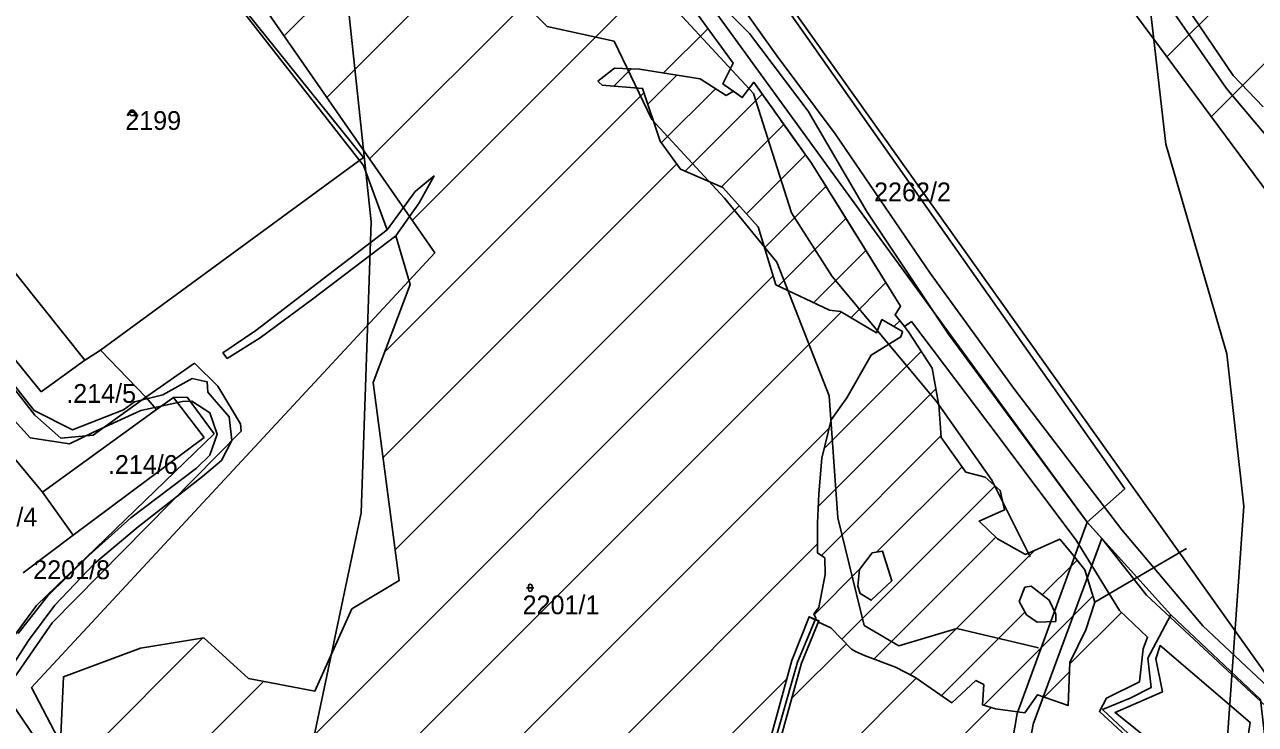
# Model space of a CAD drawing. Extents: x -564810 to -550519, y -1045831 to -1034011.
# Drawn here: x -553141.5 to -552807.2, y -1037088.7 to -1036898.7 of the extents above; entities that cross this region are included whole.
import ezdxf

# ---------------------------------------------------------------- set-up
doc = ezdxf.new("R2010")
doc.units = 0
for name, color, linetype in [('KN stav', 7, 'Continuous'), ('Lesní porost', 7, 'Continuous'), ('Odvodněné plochy', 7, 'Continuous'), ('Parcelní čísla', 7, 'Continuous'), ('Polní cesty stavající', 7, 'Continuous'), ('přeložka st silnice', 7, 'Continuous'), ('STG', 7, 'Continuous'), ('Vodní plocha', 7, 'Continuous'), ('vodní toky', 7, 'Continuous'), ('Vrstva 22', 7, 'Continuous'), ('Vrstva 33', 7, 'Continuous'), ('Vrstva 5', 7, 'Continuous'), ('zamokř ploch', 7, 'Continuous')]:
    doc.layers.add(name, color=color, linetype=linetype)

msp = doc.modelspace()

# ---------------------------------------------------------------- linework, layer by layer
at = {"layer": 'KN stav'}
for p, q in [((-553049.46, -1036934.72), (-553108.12, -1036861.74)), ((-553108.12, -1036861.74), (-553049.46, -1036934.72)), ((-552953.24, -1036867.58), (-552842.6, -1037024.79)), ((-552967.16, -1036876.79), (-552909.89, -1036955.71)), ((-552909.89, -1036955.71), (-552967.16, -1036876.79)), ((-553179.8, -1036921.43), (-553125.14, -1036989.83)), ((-553191.76, -1036930.97), (-553137.02, -1036998.43)), ((-553138.69, -1037004.7), (-553194.93, -1036933.35)), ((-553120.91, -1036987.1), (-553049.46, -1036934.72)), ((-553049.46, -1036934.72), (-553120.91, -1036987.1)), ((-552909.89, -1036955.71), (-552852.84, -1037033.78)), ((-552852.84, -1037033.78), (-552909.89, -1036955.71)), ((-553124.73, -1036989.54), (-553120.91, -1036987.1)), ((-553108.56, -1036999.88), (-553120.91, -1036987.1)), ((-553120.91, -1036987.1), (-553108.56, -1036999.88)), ((-553136.61, -1036998.14), (-553125.14, -1036989.83)), ((-553125.14, -1036989.83), (-553124.73, -1036989.54)), ((-553095.38, -1036990.58), (-553108.56, -1036999.88)), ((-553108.56, -1036999.88), (-553095.38, -1036990.58)), ((-553089.01, -1036996.83), (-553095.38, -1036990.58)), ((-553095.38, -1036990.58), (-553089.01, -1036996.83)), ((-553137.02, -1036998.43), (-553136.61, -1036998.14)), ((-553082.9, -1037007.12), (-553089.01, -1036996.83)), ((-553089.01, -1036996.83), (-553082.9, -1037007.12)), ((-553108.56, -1036999.88), (-553122.91, -1037010.18)), ((-553108.56, -1036999.88), (-553105.68, -1037003.24)), ((-553105.68, -1037003.24), (-553101.1, -1036999.92)), ((-553097.34, -1036999.88), (-553101.1, -1036999.92)), ((-553101.1, -1036999.92), (-553092.72, -1037010.79)), ((-553090.03, -1037009.79), (-553097.34, -1036999.88)), ((-553131.68, -1037010.98), (-553138.69, -1037004.7)), ((-553136.66, -1037025.67), (-553105.68, -1037003.24)), ((-553082.7, -1037009.12), (-553082.9, -1037007.12)), ((-553082.9, -1037007.12), (-553082.7, -1037009.12)), ((-553150.62, -1037008.84), (-553136.66, -1037025.67)), ((-553138.24, -1037056.46), (-553090.03, -1037009.79)), ((-553134.05, -1037061.18), (-553082.7, -1037009.12)), ((-553082.7, -1037009.12), (-553134.05, -1037061.18)), ((-553122.91, -1037010.18), (-553131.68, -1037010.98)), ((-553092.72, -1037010.79), (-553128.33, -1037037.33)), ((-552842.6, -1037024.79), (-552852.84, -1037033.78)), ((-553136.66, -1037025.67), (-553128.33, -1037037.33)), ((-552852.84, -1037033.78), (-552871.88, -1037085.78)), ((-552871.88, -1037085.78), (-552852.84, -1037033.78)), ((-552852.84, -1037033.78), (-552848.85, -1037038.19)), ((-553128.33, -1037037.33), (-553141.88, -1037047.57)), ((-552848.85, -1037038.19), (-552867.52, -1037088.69)), ((-552848.85, -1037038.19), (-552836.74, -1037053.6)), ((-552836.74, -1037053.6), (-552803.1, -1037084.94)), ((-553145.77, -1037066.62), (-553138.24, -1037056.46)), ((-553147.77, -1037081.04), (-553134.05, -1037061.18)), ((-553134.05, -1037061.18), (-553147.77, -1037081.04)), ((-552871.88, -1037085.78), (-552882.56, -1037148.8)), ((-552882.56, -1037148.8), (-552871.88, -1037085.78)), ((-552867.52, -1037088.69), (-552871.98, -1037113))]:
    msp.add_line(p, q, dxfattribs=at)
at = {"layer": 'Lesní porost'}
for p, q in [((-553071.01, -1036901.75), (-552990.73, -1036821.47)), ((-553059.41, -1036918.44), (-552978.32, -1036837.34)), ((-553047.82, -1036935.13), (-552965.78, -1036853.08)), ((-553036.23, -1036951.82), (-552964.65, -1036880.24)), ((-552967.92, -1036911.79), (-552955.85, -1036899.73)), ((-553043.69, -1036987.57), (-552973.24, -1036917.12)), ((-553044.16, -1037016.32), (-552964.35, -1036936.51)), ((-553040.87, -1037041.32), (-552947.4, -1036947.85)), ((-553108.48, -1037137.2), (-552938.17, -1036966.9)), ((-553103.39, -1037160.4), (-552919.72, -1036976.73)), ((-553070.11, -1037155.41), (-552922.98, -1037008.28)), ((-553060.69, -1037174.28), (-552926.08, -1037039.67)), ((-552850.78, -1037055.55), (-552825.91, -1037040.95)), ((-552857.62, -1037072.35), (-552843.57, -1037058.3)), ((-553127.99, -1037100.15), (-553093.08, -1037065.24)), ((-552933.14, -1037081.73), (-552918.27, -1037066.85)), ((-553118.23, -1037118.68), (-553076.6, -1037077.04)), ((-553038.67, -1037180.54), (-552934.45, -1037076.31)), ((-552949.97, -1037126.84), (-552899.29, -1037076.16)), ((-552970.05, -1037175.2), (-552878.98, -1037084.13))]:
    msp.add_line(p, q, dxfattribs=at)
for points in [[(-553142.91, -1037094.55), (-553139.29, -1037099.69), (-553142.45, -1037101.46), (-553113.25, -1037154.18), (-553102.58, -1037148.29), (-553131.8, -1037095.67), (-553130.98, -1037075.85), (-553110.01, -1037068.01), (-553092.81, -1037065.2), (-553080.66, -1037076.27), (-553062.63, -1037079.69), (-553052.57, -1037057.35), (-553039.77, -1037049.68), (-553046.85, -1036995.87), (-553036.74, -1036969.29), (-553040.68, -1036956.03), (-553034.35, -1036947.04), (-553030.25, -1036939.75), (-553035.39, -1036944.01), (-553043.05, -1036954.42), (-553049.43, -1036936.91), (-553085.28, -1036891.02)], [(-552958.5, -1036896.1), (-552948.99, -1036909.12), (-552951.83, -1036914.72), (-552946.54, -1036918.5), (-552943.44, -1036914.31), (-552927.71, -1036936.31), (-552903.54, -1036975.12), (-552905.06, -1036977.48), (-552902.52, -1036980.62), (-552900.59, -1036979.32), (-552879.86, -1037006.72), (-552855.84, -1037038.66), (-552844.11, -1037057.79), (-552836.45, -1037065), (-552837.66, -1037068.23), (-552838.67, -1037077.19), (-552847.62, -1037081.64), (-552849.55, -1037085.22)], [(-552939.26, -1037103.77), (-552930.48, -1037072.14), (-552925.72, -1037060.62), (-552928.41, -1037059.51), (-552933.09, -1037071.34), (-552941.77, -1037103.14)], [(-552810.24, -1037099.06), (-552808.61, -1037088.2), (-552833.03, -1037067.34), (-552834.22, -1037070.92), (-552832.38, -1037079.88), (-552845.29, -1037085.51), (-552828.27, -1037099.13)], [(-552849.55, -1037085.22), (-552830.17, -1037103.17), (-552816.47, -1037118.81), (-552817.67, -1037133.71), (-552823.79, -1037143.46), (-552852.83, -1037178.07), (-552873.47, -1037198.62), (-552891.1, -1037218.45), (-552901.83, -1037239.56), (-552906.62, -1037243.7), (-552906.02, -1037249.45), (-552916.79, -1037279.9), (-552921.02, -1037281.63), (-552922.55, -1037284.1), (-552922.87, -1037294.35), (-552927.53, -1037313.12), (-552933.23, -1037342.22), (-552937.38, -1037370), (-552936.66, -1037373.95)]]:
    msp.add_lwpolyline(points, dxfattribs=at)
at = {"layer": 'Odvodněné plochy'}
msp.add_lwpolyline([(-551958.26, -1037299.6), (-552014.39, -1037387.96), (-552071.44, -1037439.67), (-552181.86, -1037352.69), (-552220.51, -1037328.76), (-552305.17, -1037262.49), (-552417.43, -1037128.11), (-552540.73, -1037034.23), (-552612.51, -1036967.96), (-552627.23, -1037012.14), (-552687.96, -1037100.5), (-552930.89, -1036772.83)], dxfattribs=at)
at = {"layer": 'Polní cesty stavající'}
for p, q in [((-552813.18, -1036912.44), (-552855.7, -1036849.82)), ((-552859.35, -1036851.96), (-552815.01, -1036915.99)), ((-552805.04, -1036920.98), (-552813.18, -1036912.44)), ((-552815.01, -1036915.99), (-552777.75, -1036960.4))]:
    msp.add_line(p, q, dxfattribs=at)
for points in [[(-553168.93, -1036965.42), (-553138.92, -1037003.49), (-553128.48, -1037008.7), (-553114.68, -1037003.31), (-553111.69, -1037001.07), (-553103.94, -1036999.25), (-553096.03, -1036994.82), (-553091.92, -1036995.64), (-553091.7, -1036998.53), (-553085.93, -1037005.2), (-553085.2, -1037011.59), (-553088.05, -1037017.03), (-553093.14, -1037021.41), (-553110.66, -1037035.09), (-553122.55, -1037044.98), (-553133.33, -1037056.36), (-553140.45, -1037065.93), (-553146.62, -1037075.52)], [(-553143.23, -1037064.08), (-553135.24, -1037053.88), (-553124.09, -1037042.84), (-553112.68, -1037032.66), (-553094.83, -1037019.16), (-553091.16, -1037015.57), (-553089.23, -1037009.91), (-553091.19, -1037004.1), (-553096.04, -1037000.9), (-553098.57, -1037001), (-553109.94, -1037003.45), (-553123.01, -1037009.48), (-553129.3, -1037012.54), (-553139.96, -1037010.87), (-553144.33, -1037006.11)], [(-553147.02, -1037079.93), (-553135.16, -1037097.46), (-553139.29, -1037099.69), (-553142.91, -1037094.55)]]:
    msp.add_lwpolyline(points, dxfattribs=at)
at = {"layer": 'přeložka st silnice'}
for p, q in [((-552831.15, -1036907.36), (-552711.44, -1036787.65)), ((-552819.1, -1036923.6), (-552699.32, -1036803.82))]:
    msp.add_line(p, q, dxfattribs=at)
at = {"layer": 'STG'}
for points in [[(-553086.83, -1037509.03), (-553102.44, -1037299.55), (-553086.83, -1037209.51), (-553071.21, -1037131.41), (-553050.08, -1037031.26), (-553047.33, -1036952.24), (-553054.68, -1036883.33), (-553078.56, -1036837.39), (-553119.89, -1036809.83), (-553157.55, -1036794.21), (-553196.13, -1036789.62), (-553152.96, -1036760.21), (-553125.41, -1036746.43), (-553070.29, -1036720.71), (-552977.52, -1036697.74), (-552896.69, -1036677.52), (-552848, -1036668.34), (-552776.36, -1036649.96), (-552684.5, -1036608.61), (-552638.57, -1036588.4), (-552609.18, -1036560.84), (-552571.52, -1036514.9), (-552546.72, -1036489.17)], [(-552837.9, -1036875.06), (-552831.47, -1036931.11), (-552814.94, -1036988.08), (-552810.34, -1037029.42), (-552815.85, -1037107.52), (-552838.82, -1037208.59), (-552862.7, -1037291.28), (-552904.04, -1037418.07)]]:
    msp.add_lwpolyline(points, dxfattribs=at)
at = {"layer": 'Vodní plocha'}
for p, q in [((-552981.29, -1036910.47), (-552985.78, -1036914.03)), ((-552981.43, -1036915.36), (-552976.72, -1036910.65)), ((-552974.5, -1036910.73), (-552981.29, -1036910.47)), ((-552957.98, -1036913.4), (-552974.5, -1036910.73)), ((-552972.2, -1036920.27), (-552964.31, -1036912.38)), ((-552950.91, -1036917.95), (-552957.98, -1036913.4)), ((-552968.56, -1036930.77), (-552953.85, -1036916.06)), ((-552962.08, -1036938.43), (-552941.15, -1036917.51)), ((-552948.96, -1036916.77), (-552950.91, -1036917.95)), ((-552937.51, -1036922.6), (-552938.38, -1036921.38)), ((-552936.64, -1036923.82), (-552937.51, -1036922.6)), ((-552952.22, -1036942.71), (-552935.26, -1036925.75)), ((-552945.42, -1036950.06), (-552929.36, -1036934)), ((-552923.88, -1036942.46), (-552924.67, -1036941.19)), ((-552940.51, -1036959.28), (-552923.8, -1036942.58)), ((-552921.5, -1036946.28), (-552922.29, -1036945.01)), ((-552903.54, -1036975.12), (-552921.5, -1036946.28)), ((-552936.72, -1036969.64), (-552918.38, -1036951.3)), ((-552927.12, -1036974.18), (-552912.95, -1036960.01)), ((-552917.06, -1036978.27), (-552907.52, -1036968.73)), ((-552905.06, -1036977.48), (-552903.54, -1036975.12)), ((-552908.63, -1036978.78), (-552902.98, -1036982.04)), ((-552905.34, -1036980.68), (-552903.75, -1036979.1)), ((-552902.98, -1036982.04), (-552902.99, -1036982.08)), ((-552924.27, -1037013.76), (-552897.95, -1036987.44)), ((-552925.9, -1037029.53), (-552893.98, -1036997.61)), ((-552925.07, -1037042.84), (-552892.53, -1037010.3)), ((-552909.99, -1037041.9), (-552886.85, -1037018.76)), ((-552919.52, -1037065.57), (-552877.89, -1037023.95)), ((-552910.79, -1037070.99), (-552877.68, -1037037.88)), ((-552900.9, -1037075.25), (-552867.08, -1037041.43)), ((-552865.05, -1037053.53), (-552855.62, -1037044.11)), ((-552853.5, -1037046.72), (-552857.07, -1037042.32)), ((-552927.02, -1037058.93), (-552914.67, -1037046.58)), ((-552871.37, -1037055.38), (-552869.76, -1037051.43)), ((-552869.76, -1037051.43), (-552868.05, -1037051.2)), ((-552868.05, -1037051.2), (-552863.15, -1037055)), ((-552880.89, -1037083.51), (-552851.28, -1037053.91)), ((-552863.15, -1037055), (-552861.4, -1037058.76)), ((-552892.42, -1037080.9), (-552869.76, -1037058.25)), ((-552869.38, -1037058.93), (-552871.37, -1037055.38)), ((-552926.44, -1037060.32), (-552925.72, -1037060.62)), ((-552925.72, -1037060.62), (-552925.88, -1037061)), ((-552866.44, -1037060.96), (-552869.38, -1037058.93)), ((-552861.36, -1037060.79), (-552866.44, -1037060.96)), ((-552861.4, -1037058.76), (-552861.36, -1037060.79)), ((-552904.96, -1037073.14), (-552899.7, -1037075.87)), ((-552904.96, -1037073.14), (-552899.7, -1037075.87)), ((-552864.55, -1037081.32), (-552857.7, -1037074.47))]:
    msp.add_line(p, q, dxfattribs=at)
for points in [[(-552985.78, -1036914.03), (-552985.48, -1036914.3), (-552984.58, -1036915.1), (-552973.61, -1036915.99), (-552968.89, -1036930.31), (-552963.33, -1036937.89), (-552951.87, -1036942.86), (-552942.25, -1036953.6), (-552937.43, -1036969.3), (-552922.89, -1036976.19), (-552919.91, -1036976.62), (-552910.05, -1036982.33), (-552908.63, -1036978.78)], [(-552938.38, -1036921.38), (-552939.25, -1036920.16), (-552940.13, -1036918.95), (-552943.44, -1036914.31), (-552946.54, -1036918.5), (-552948.96, -1036916.77)], [(-552927.71, -1036936.31), (-552935.77, -1036925.04), (-552936.64, -1036923.82)], [(-552924.67, -1036941.19), (-552925.46, -1036939.92), (-552927.71, -1036936.31)], [(-552922.29, -1036945.01), (-552923.09, -1036943.74), (-552923.88, -1036942.46)], [(-552857.07, -1037042.32), (-552860.31, -1037038.41), (-552869.63, -1037042.56), (-552877.2, -1037038.34), (-552882.24, -1037033.55), (-552875.3, -1037030.49), (-552876.48, -1037025.21), (-552880.57, -1037021.55), (-552885.78, -1037020.26), (-552892.49, -1037010.83), (-552893.03, -1037003.18), (-552893.07, -1037002.59), (-552893.26, -1037001.57), (-552895, -1036991.99), (-552901.4, -1036982.11), (-552902.52, -1036980.62), (-552905.06, -1036977.48)], [(-552902.99, -1036982.08), (-552903.44, -1036983.46), (-552911.54, -1036988.43), (-552918.11, -1037000.05), (-552922.44, -1037005.99), (-552924.9, -1037016.44), (-552925.77, -1037026.07), (-552926.07, -1037034.11), (-552926.09, -1037042.13), (-552924.11, -1037043.51), (-552923.99, -1037048.04), (-552925.73, -1037057.02), (-552927.13, -1037058.7)], [(-552915.18, -1037051.2), (-552914.71, -1037046.64), (-552911.3, -1037042.13), (-552908.49, -1037041.64), (-552905.88, -1037049.73), (-552911.51, -1037055.01), (-552914.49, -1037053.2), (-552915.18, -1037051.2)], [(-552899.7, -1037075.87), (-552889.61, -1037082.84), (-552883.06, -1037076.8), (-552880.91, -1037077.91), (-552881.33, -1037083.37), (-552877.75, -1037084.53), (-552869.77, -1037085.56), (-552866.39, -1037080.67), (-552858.05, -1037083.6), (-552857.6, -1037071.89), (-552853.19, -1037063.06), (-552850.78, -1037055.55), (-552853.5, -1037046.72)], [(-552927.13, -1037058.7), (-552926.58, -1037059.85), (-552926.44, -1037060.32)], [(-552925.88, -1037061), (-552922.51, -1037062.51), (-552916.87, -1037068.28), (-552915.76, -1037068.93), (-552913.34, -1037070.04), (-552904.96, -1037073.14)]]:
    msp.add_lwpolyline(points, dxfattribs=at)
at = {"layer": 'vodní toky'}
for points in [[(-552800.88, -1037081.28), (-552821.47, -1037061.91), (-552843.47, -1037035.87), (-552872.55, -1036997.9), (-552895.54, -1036966.17), (-552921.29, -1036928.34), (-552937.05, -1036907.22), (-552948.58, -1036890.99)], [(-552958.5, -1036896.1), (-552948.99, -1036909.12), (-552951.83, -1036914.72), (-552946.54, -1036918.5), (-552943.44, -1036914.31), (-552927.71, -1036936.31), (-552903.54, -1036975.12), (-552905.06, -1036977.48), (-552902.52, -1036980.62), (-552900.59, -1036979.32), (-552879.86, -1037006.72), (-552855.84, -1037038.66), (-552844.11, -1037057.79), (-552836.45, -1037065), (-552837.66, -1037068.23), (-552838.67, -1037077.19), (-552847.62, -1037081.64), (-552849.55, -1037085.22), (-552830.17, -1037103.17), (-552816.47, -1037118.81)], [(-552939.26, -1037103.77), (-552930.48, -1037072.14), (-552925.72, -1037060.62), (-552926.77, -1037060.36), (-552928.41, -1037059.51), (-552933.09, -1037071.34), (-552941.77, -1037103.14)]]:
    msp.add_lwpolyline(points, dxfattribs=at)
for points in [[(-553086.52, -1036989.31), (-553087.62, -1036987.85), (-553078.7, -1036981.72), (-553066.21, -1036972.17), (-553043.05, -1036954.42), (-553035.39, -1036944.01), (-553030.25, -1036939.75), (-553034.35, -1036947.04), (-553040.68, -1036956.03), (-553063.32, -1036973.27), (-553077.53, -1036983.72)], [(-552821.11, -1037109.83), (-552828.27, -1037099.13), (-552845.29, -1037085.51), (-552832.38, -1037079.88), (-552834.22, -1037070.92), (-552833.03, -1037067.34), (-552808.61, -1037088.2), (-552810.24, -1037099.06), (-552812.35, -1037102.93), (-552817.59, -1037107.53)]]:
    msp.add_lwpolyline(points, close=True, dxfattribs=at)
at = {"layer": 'Vrstva 33'}
for points in [[(-552868.3, -1037043.25), (-552878.76, -1037022.38), (-552893.75, -1037001.06), (-552922.17, -1036967.11), (-552933.21, -1036949.74), (-552943.47, -1036917.37), (-552963.99, -1036895.26), (-552986.09, -1036881.05), (-553001.88, -1036881.84), (-553006.61, -1036892.1), (-552999.51, -1036899.21), (-552981.36, -1036903.15), (-552971.1, -1036924.47), (-552951.37, -1036945.79), (-552937.16, -1036963.16), (-552922.95, -1036999.48), (-552920.59, -1037032.64), (-552913.48, -1037061.85), (-552904.01, -1037067.38), (-552888.23, -1037062.64), (-552866.12, -1037067.96)], [(-552830.71, -1037101.5), (-552848.67, -1037084.69), (-552841.14, -1037081.64), (-552835.49, -1037078.74), (-552836.36, -1037070.77), (-552830.13, -1037058.95), (-552852.84, -1037033.78), (-552890.54, -1036982.73), (-552912.62, -1036949.63), (-552928.61, -1036922.15), (-552944.59, -1036901.07), (-552960.57, -1036885.08)], [(-552926.77, -1037060.36), (-552931.51, -1037071.8), (-552940.64, -1037103.56), (-552946.14, -1037117.24), (-552953.45, -1037129.69), (-552957.12, -1037142.53), (-552964.42, -1037148.54), (-552972.11, -1037150.76), (-552988.02, -1037163.81), (-553020.87, -1037172.43), (-553029.98, -1037177.29), (-553059.12, -1037192.99), (-553070.41, -1037202.83)], [(-552814.33, -1037119.11), (-552803.47, -1037101.72), (-552805.79, -1037082), (-552830.13, -1037058.95)]]:
    msp.add_lwpolyline(points, dxfattribs=at)
at = {"layer": 'Vrstva 5'}
for points in [[(-553153.82, -1036717.79), (-553120.78, -1036720.53), (-553077.61, -1036697.47), (-552948.67, -1036872.18), (-552799.53, -1037081.76), (-552742.11, -1037143.32), (-552838.62, -1037227.28), (-552866, -1037405.86)], [(-553199.99, -1037048.7), (-553110.11, -1037156.36), (-553101.22, -1037152.15), (-553139.6, -1037078.66), (-553030.07, -1036960.69), (-553100.28, -1036859.58), (-553193.44, -1036929.8)]]:
    msp.add_lwpolyline(points, dxfattribs=at)
at = {"layer": 'zamokř ploch'}
for p, q in [((-553112.28, -1036923.38), (-553110.68, -1036923.38)), ((-553005.15, -1037051.63), (-553003.15, -1037051.63)), ((-553004.65, -1037051.13), (-553004.65, -1037052.13)), ((-553003.65, -1037051.13), (-553003.65, -1037052.13))]:
    msp.add_line(p, q, dxfattribs=at)
msp.add_circle((-553112.28, -1036922.63), 0.75, dxfattribs=at)
for centre, start, end in [((-553004.15, -1037051.13), 0, 180), ((-553004.15, -1037052.13), 180, 0)]:
    msp.add_arc(centre, 0.5, start, end, dxfattribs=at)

# ---------------------------------------------------------------- texts
at = {"layer": 'Parcelní čísla'}
for s, p in [('2199', (-553114.16, -1036927.26)), ('2262/2', (-552910.74, -1036946.64)), ('2201/8', (-553139.16, -1037049.27)), ('2201/1', (-553006.22, -1037058.8))]:
    msp.add_text(s, height=5.1, dxfattribs=at).set_placement(p)
at = {"layer": 'Vrstva 22'}
for s, p in [('.214/5', (-553130.19, -1037001.39)), ('.214/6', (-553118.88, -1037020.68)), ('.214/4', (-553157.01, -1037034.94))]:
    msp.add_text(s, height=5.1, dxfattribs=at).set_placement(p)

doc.saveas('drawing.dxf')
